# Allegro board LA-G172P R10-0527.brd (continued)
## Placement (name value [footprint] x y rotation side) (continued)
CT361  1U_0201_6.3V6K  [C_0201]  17.37 38.84 180 top
CT362  470P_0402_50V7K  [C_0402]  14.5 39.03 0 top
CT363  0.1U_0201_10V6K  [C_0201]  12.42 37.86 270 top
CT365  47U_0603_6.3V6M  [C_0603]  17.11 44.61 0 top
CT366  47U_0603_6.3V6M  [C_0603]  285.21 36.36 270 top
CV633  2200P_0402_50V7K  [C_0402]  123.91 80.45 0 bottom
CV651  2200P_0402_50V7K  [C_0402]  132.25 83.65 0 bottom
CW1  0.1U_0201_10V6K  [C_0201]  191.17 69.91 90 bottom
CW2  0.01U_0201_16V7  [C_0201]  179.29 69.98 90 bottom
CW3  10U_0402_10V6M  [C_0402]  176.96 68.64 180 bottom
CW4  15P_0201_50V8J  [C_0201]  190.6 69.91 90 bottom
CW5  2P_0201_25V8B  [C_0201]  98.9 76.31 270 bottom
CW6  2P_0201_25V8B  [C_0201]  97.71 76.94 180 bottom
CW7  2P_0201_25V8B  [C_0201]  198.5 77.44 90 bottom
CW8  2P_0201_25V8B  [C_0201]  200.35 78.13 180 bottom
CW9  10U_0402_10V6M  [C_0402]  191.4 68.64 180 bottom
CW10  0.01U_0201_16V7  [C_0201]  191.74 69.91 90 bottom
CW11  15P_0201_50V8J  [C_0201]  178.72 69.98 90 bottom
CW12  0.1U_0201_10V6K  [C_0201]  178.15 69.98 90 bottom
D1  -  [BAT54CW_SOT323-3]  104.87 66.05 0 top
D2  -  [BAT54CW_SOT323-3]  187.44 39.95 90 top
D3  -  [BAT54CW_SOT323-3]  187.23 42.9 270 top
D12  -  [RB751V40_SC76-2]  235.06 5.2 270 top
D13  AZ5B75-01B.R7G_CSP0603P2Y2  [AZ5B75-01BPR7G_CSP0603P2Y2]  61.06 16.37 270 top
D14  AZ5B75-01B.R7G_CSP0603P2Y2  [AZ5B75-01BPR7G_CSP0603P2Y2]  61.06 17.11 90 top
D16  -  [TVNST52302AB0_SOT523-3]  62.25 14.51 270 top
D20  -  [RB751S40T1G_SOD523-2]  235.49 16.08 90 top
D21  -  [RB751S40T1G_SOD523-2]  186.15 46.48 270 top
D23  -  [BAT54CW_SOT323-3]  175.74 59.6 180 top
D50  PESD5V0H1BSF_SOD962-2-2  [ESD101-B1-02ELS_TSSLP-2-4-2]  256.38 11.36 270 top
D51  PESD5V0H1BSF_SOD962-2-2  [ESD101-B1-02ELS_TSSLP-2-4-2]  254.99 11.36 270 top
D75  PESD5V0H1BSF_SOD962-2-2  [ESD101-B1-02ELS_TSSLP-2-4-2]  12.8 65.47 90 top
D76  PESD5V0H1BSF_SOD962-2-2  [ESD101-B1-02ELS_TSSLP-2-4-2]  12.91 59.14 90 bottom
D77  PESD5V0H1BSF_SOD962-2-2  [ESD101-B1-02ELS_TSSLP-2-4-2]  12.8 64.85 270 top
D78  PESD5V0H1BSF_SOD962-2-2  [ESD101-B1-02ELS_TSSLP-2-4-2]  12.91 60.55 270 bottom
D79  PESD5V0H1BSF_SOD962-2-2  [ESD101-B1-02ELS_TSSLP-2-4-2]  13.92 64.98 90 bottom
D80  PESD5V0H1BSF_SOD962-2-2  [ESD101-B1-02ELS_TSSLP-2-4-2]  11.9 57.97 0 top
D81  PESD5V0H1BSF_SOD962-2-2  [ESD101-B1-02ELS_TSSLP-2-4-2]  13.92 64.36 270 bottom
D82  PESD5V0H1BSF_SOD962-2-2  [ESD101-B1-02ELS_TSSLP-2-4-2]  13.3 57.97 180 top
D83  PESD5V0H1BSF_SOD962-2-2  [ESD101-B1-02ELS_TSSLP-2-4-2]  280.63 69.8 315 top
D84  PESD5V0H1BSF_SOD962-2-2  [ESD101-B1-02ELS_TSSLP-2-4-2]  275.83 71.44 315 bottom
D85  PESD5V0H1BSF_SOD962-2-2  [ESD101-B1-02ELS_TSSLP-2-4-2]  280.19 70.24 135 top
D86  PESD5V0H1BSF_SOD962-2-2  [ESD101-B1-02ELS_TSSLP-2-4-2]  276.83 70.44 135 bottom
D87  PESD5V0H1BSF_SOD962-2-2  [ESD101-B1-02ELS_TSSLP-2-4-2]  280.63 69.8 315 bottom
D88  PESD5V0H1BSF_SOD962-2-2  [ESD101-B1-02ELS_TSSLP-2-4-2]  275.92 71.09 315 top
D89  PESD5V0H1BSF_SOD962-2-2  [ESD101-B1-02ELS_TSSLP-2-4-2]  280.19 70.24 135 bottom
D90  PESD5V0H1BSF_SOD962-2-2  [ESD101-B1-02ELS_TSSLP-2-4-2]  276.92 70.09 135 top
D116  RB751S40T1G_SOD523-2  [RB520SM-30T2R_EMD2-2]  179.46 16.36 0 top
D132  -  [RB751V40_SC76-2]  65.56 17.27 270 top
D407  PESD5V0H1BSF_SOD962-2-2  [ESD101-B1-02ELS_TSSLP-2-4-2]  11.58 62.83 90 top
D408  PESD5V0H1BSF_SOD962-2-2  [ESD101-B1-02ELS_TSSLP-2-4-2]  11.58 61.81 90 top
D409  PESD5V0H1BSF_SOD962-2-2  [ESD101-B1-02ELS_TSSLP-2-4-2]  12.91 61.95 270 bottom
D410  PESD5V0H1BSF_SOD962-2-2  [ESD101-B1-02ELS_TSSLP-2-4-2]  12.91 62.96 270 bottom
D411  PESD5V0H1BSF_SOD962-2-2  [ESD101-B1-02ELS_TSSLP-2-4-2]  12.35 63.66 0 top
D412  PESD5V0H1BSF_SOD962-2-2  [ESD101-B1-02ELS_TSSLP-2-4-2]  11.58 60.73 90 top
D413  PESD5V0H1BSF_SOD962-2-2  [ESD101-B1-02ELS_TSSLP-2-4-2]  12.59 66.99 90 top
D414  PESD5V0H1BSF_SOD962-2-2  [ESD101-B1-02ELS_TSSLP-2-4-2]  13.56 64.05 270 top
D415  PESD5V0H1BSF_SOD962-2-2  [ESD101-B1-02ELS_TSSLP-2-4-2]  278.17 69.24 0 top
D416  PESD5V0H1BSF_SOD962-2-2  [ESD101-B1-02ELS_TSSLP-2-4-2]  277.15 69.24 0 top
D417  PESD5V0H1BSF_SOD962-2-2  [ESD101-B1-02ELS_TSSLP-2-4-2]  278.16 70.31 135 bottom
D418  PESD5V0H1BSF_SOD962-2-2  [ESD101-B1-02ELS_TSSLP-2-4-2]  278.88 69.59 135 bottom
D419  PESD5V0H1BSF_SOD962-2-2  [ESD101-B1-02ELS_TSSLP-2-4-2]  273.4 63.45 180 bottom
D420  PESD5V0H1BSF_SOD962-2-2  [ESD101-B1-02ELS_TSSLP-2-4-2]  273.2 69.12 0 top
D421  PESD5V0H1BSF_SOD962-2-2  [ESD101-B1-02ELS_TSSLP-2-4-2]  272.12 69.12 0 top
D422  PESD5V0H1BSF_SOD962-2-2  [ESD101-B1-02ELS_TSSLP-2-4-2]  272.17 63.5 180 bottom
D438  -  [RB751S40T1G_SOD523-2]  204.78 54.08 180 top
D444  PESD5V0H1BSF_SOD962-2-2  [ESD101-B1-02ELS_TSSLP-2-4-2]  163.99 80.53 90 bottom
D445  PESD5V0H1BSF_SOD962-2-2  [ESD101-B1-02ELS_TSSLP-2-4-2]  165.01 80.53 90 bottom
D446  PESD5V0H1BSF_SOD962-2-2  [ESD101-B1-02ELS_TSSLP-2-4-2]  162.15 80.53 90 bottom
D447  PESD5V0H1BSF_SOD962-2-2  [ESD101-B1-02ELS_TSSLP-2-4-2]  163.16 80.53 90 bottom
D448  PESD5V0H1BSF_SOD962-2-2  [ESD101-B1-02ELS_TSSLP-2-4-2]  161.07 80.53 90 bottom
D449  PESD5V0H1BSF_SOD962-2-2  [ESD101-B1-02ELS_TSSLP-2-4-2]  160.05 80.53 90 bottom
D450  PESD5V0H1BSF_SOD962-2-2  [ESD101-B1-02ELS_TSSLP-2-4-2]  158.53 79.26 90 bottom
D459  AZ4520-01F.R7G_DFN1610P2E2  [AZ4520-01FPR7G_DFN1610P2E2]  8.69 54.4 180 top
D460  AZ4520-01F.R7G_DFN1610P2E2  [AZ4520-01FPR7G_DFN1610P2E2]  283.64 62.42 0 top
D461  LMBR4010H3T5G DFN-1608  [NSR20F30NXT5G_DSN2-2]  9.73 17.51 315 bottom
D462  LMBR4010H3T5G DFN-1608  [NSR20F30NXT5G_DSN2-2]  272.82 16.28 90 top
D465  PESD5V0H1BSF_SOD962-2-2  [ESD101-B1-02ELS_TSSLP-2-4-2]  130.78 81.48 90 bottom
D466  PESD5V0H1BSF_SOD962-2-2  [ESD101-B1-02ELS_TSSLP-2-4-2]  129.13 81.48 90 bottom
D468  -  [RB751S40T1G_SOD523-2]  186.32 35.91 0 top
D469  -  [BZT52C6V2LP-7_X1-DFN1006-2-2]  70.33 6.67 270 top
D470  -  [BZT52C6V2LP-7_X1-DFN1006-2-2]  233.3 10.39 180 top
D471  PESD5V0H1BSF_SOD962-2-2  [ESD101-B1-02ELS_TSSLP-2-4-2]  129.95 81.48 90 bottom
D472  PESD5V0H1BSF_SOD962-2-2  [ESD101-B1-02ELS_TSSLP-2-4-2]  254.16 11.36 270 top
D473  PESD5V0H1BSF_SOD962-2-2  [ESD101-B1-02ELS_TSSLP-2-4-2]  253.33 11.36 270 top
D474  -  [RB751S40T1G_SOD523-2]  203.21 52.81 0 top
D475  -  [RB751S40T1G_SOD523-2]  203.21 51.54 0 top
D476  PESD5V0H1BSF_SOD962-2-2  [ESD101-B1-02ELS_TSSLP-2-4-2]  250.44 10.39 0 top
D477  PESD5V0H1BSF_SOD962-2-2  [ESD101-B1-02ELS_TSSLP-2-4-2]  251.83 10.39 180 top
D481  -  [RB751V40_SC76-2]  206.76 64.25 270 bottom
DA1  -  [ESD207-B1-02EL_TSLP-2-19-2]  10.06 74.87 90 bottom
DA3  -  [ESD207-B1-02EL_TSLP-2-19-2]  5.37 74.2 180 bottom
DA4  -  [ESD207-B1-02EL_TSLP-2-19-2]  13.35 71.79 0 top
DA5  -  [ESD207-B1-02EL_TSLP-2-19-2]  5.37 75.22 180 bottom
DA8  AZ5B75-01B.R7G_CSP0603P2Y2  [AZ5B75-01BPR7G_CSP0603P2Y2]  13.75 5.64 0 bottom
DA9  AZ5B75-01B.R7G_CSP0603P2Y2  [AZ5B75-01BPR7G_CSP0603P2Y2]  12.04 5.64 0 bottom
DA10  -  [RB751S40T1G_SOD523-2]  27.59 11.62 270 top
DA11  AZ5125-01H.R7G_SOD523-2  [AZ5125-01HPR7G_SOD523-2]  39.91 14.5 270 top
DA13  -  [ESD207-B1-02EL_TSLP-2-19-2]  11.74 67.93 270 top
DA14  AZ5B75-01B.R7G_CSP0603P2Y2  [AZ5B75-01BPR7G_CSP0603P2Y2]  8.59 5.62 0 bottom
DA15  AZ5B75-01B.R7G_CSP0603P2Y2  [AZ5B75-01BPR7G_CSP0603P2Y2]  10.32 5.64 0 bottom
DC1  RB751S40T1G_SOD523-2  [RB520SM-30T2R_EMD2-2]  179.29 51.96 90 top
DC2  RB751S40T1G_SOD523-2  [RB520SM-30T2R_EMD2-2]  180.56 53.65 270 top
DE1  -  [RB520SM-30T2R_EMD2-2]  211.77 47.66 0 top
DE2  -  [RB520SM-30T2R_EMD2-2]  220.68 63.05 180 top
DE3  -  [RB520SM-30T2R_EMD2-2]  218.97 46.01 90 top
DE4  -  [RB520SM-30T2R_EMD2-2]  221.2 56.07 270 top
DE5  -  [RB520SM-30T2R_EMD2-2]  211.77 46.46 0 top
DT1  -  [1N4148WS-L_SOD323-2]  9.66 25.44 135 top
DT2  -  [1N4148WS-L_SOD323-2]  258.7 19.4 180 top
DV11  RB751S40T1G_SOD523-2  [RB520SM-30T2R_EMD2-2]  123.62 81.49 0 bottom
DV12  RB751S40T1G_SOD523-2  [RB520SM-30T2R_EMD2-2]  131.25 83.67 180 bottom
DZ3  -  [RB751S40T1G_SOD523-2]  196.91 61.31 180 top
DZ4  -  [RB751S40T1G_SOD523-2]  196.91 60.04 180 top
F1  0.5A_65V_T0603FF0500TM  [F_T0603FF0500TM]  68.32 19.92 90 top
F2  0438.500WR 0.5A 32V UL/CSA  [R_0603]  63.3 18.11 180 top
F3  3A_32V_F0603FA3000V032T  [F_F0603FA3000V032T]  100.86 70.97 180 top
F4  1A_65V_T0603FF1000TM  [F_T0603FF1000TM]  173.32 70.28 90 top
F5  0.5A_65V_T0603FF0500TM  [F_T0603FF0500TM]  165.96 82.15 90 bottom
FD1  -  [FIDUCIAL_C40M80]  19.53 66.14 0 top
FD2  -  [FIDUCIAL_C40M80]  274.31 46.38 0 top
FD3  -  [FIDUCIAL_C40M80]  19.65 64.74 180 bottom
FD4  -  [FIDUCIAL_C40M80]  282.35 3.47 180 bottom
H1  H_2P0  [H_2P0-G]  2.9 71.75 0 top
H2  H_2P0  [H_2P0-G]  26.8 57.75 0 top
H3  H_2P0  [H_2P0-G]  24.13 29.27 0 top
H4  -  [H_2P0]  64.38 21.91 0 top
H5  -  [H_2P4]  232.12 20.4 0 top
H6  H_2P0  [H_2P0-G]  268.67 29.27 0 top
H7  H_2P0  [H_2P0-G]  266 57.75 0 top
H8  H_2P9  [H_2P9-G]  2.9 53.35 0 top
H9  H_2P0  [H_2P0-G]  118.26 46.9 0 top
H10  H_2P0  [H_2P0-G]  182.54 46.9 0 top
H11  H_2P0  [H_2P0-G]  118.26 25.17 0 top
H12  H_2P0  [H_2P0-G]  182.54 25.17 0 top
H13  -  [H_2P4]  117.83 20.4 0 top
H14  -  [H_2P6]  176.4 78.95 0 top
H15  -  [H_2P6]  110.55 78.95 0 top
H16  H_2P6  [H_2P6-G]  195.05 71.85 0 top
H17  H_1P9  [H_1P9-G]  19.05 71.25 0 top
H18  H_1P9  [H_1P9-G]  92.27 71.85 0 top
H19  H_1P9  [H_1P9-G]  148.5 80 0 top
H20  H_1P9  [H_1P9-G]  200.55 71.85 0 top
H21  H_1P9  [H_1P9-G]  287.9 83.35 0 top
H22  -  [H_2P4]  222.6 2.35 0 top
H23  -  [H_2P4]  70.2 2.35 0 top
H24  -  [H_2P4]  2.18 3.11 0 top
H25  -  [H_2P4]  290.62 3.11 0 top
H27  -  [H_1P3N]  291.25 7.3 0 top
H29  -  [H_2P5X5P5N]  148.5 76.15 90 top
H33  -  [H_0P5X2P3N]  141.3 1.7 90 top
H34  -  [H_0P4X2P2N]  222.79 41 180 top
H35  -  [H_0P5X2P3N]  151.4 73.7 90 top
H36  -  [H_0P5X2P3N]  141.3 73.7 90 top
H37  -  [H_0P5X2P3N]  79.55 73.7 90 top
H38  -  [H_0P5X2P3N]  151.4 1.7 90 top
JANTL1  RF_SPRING  [CLIP_2X2P5-NP]  97.96 80.19 90 top
JANTL3  BELLW_10093-1021  [BELLW_10093-1021_4P]  109.57 74.25 90 bottom
JANTR1  BELLW_10093-1021  [BELLW_10093-1021_4P]  177.38 74.25 270 bottom
JANTR3  RF_SPRING  [CLIP_2X2P5-NP]  201.03 80.19 90 top
JAPS1  ACES_50506-01841-P01  [ACES_50506-01841-P01_18P]  217.39 62.77 270 bottom
JCR1  T-SOL_158-9090302600  [T-SOL_158-9090302600_18P-T]  276.79 51.04 90 top
JDB1  ACES_50521-01041-P01  [ACES_50521-01041-P01_10P]  11 32.71 90 bottom
JDB2  ACES_50521-01041-P01  [ACES_50521-01041-P01_10P]  256.23 10.41 0 bottom
JDB3  JXT_FP241AH-006GAAM  [JXT_FP241AH-006GAAM_6P]  7.29 45.59 90 bottom
JDB4  JXT_FP241AH-006GAAM  [JXT_FP241AH-006GAAM_6P]  287.35 27.07 270 bottom
JDEBUG1  ACES_50521-01041-P01  [ACES_50521-01041-P01_10P]  229.18 7.82 270 top
JDEBUG2  ACES_50521-01041-P01  [ACES_50521-01041-P01_10P]  208.03 69.14 0 bottom
JDEG1  -  [ACES_50521-01041-P01_10P]  230.69 3.31 90 top
JEDP1  I-PEX_20879-040E-01  [I-PEX_20879-040E-01_40P-T]  140.9 83.92 0 top
JFAN1  CVILU_CF35042D0RD-NH  [CVILU_CF35042D0RD-NH_4P-T]  63.45 2.64 180 top
JFAN2  CVILU_CF35042D0RD-NH  [CVILU_CF35042D0RD-NH_4P-T]  237.65 2.85 180 top
JFP1  TWVM_FPC0510-08RC-TAGHA  [TWVM_FPC0510-08RC-TAGHA_8P]  57.95 14.85 270 top
JHP1  UNIMI_FCECBE015  [UNIMI_FCECBE015_6P-T]  8.22 75.1 90 top
JIO1  ACES_51515-0510M-P01  [ACES_51515-0510M-P01_51P-T]  243.65 5.63 0 top
JMIPI60  SAMTE_QSH-030-01-L-D-A  [SAMTE_QSH-030-01-H-D-A_60P-T]  110 11.99 0 bottom
JNGFF1  BELLW_80149-2021  [BELLW_80149-2021_67P-S]  218.64 12.8 180 bottom
JRTC1  ACES_50278-00201-001  [ACES_50278-00201-001_2P]  56.57 11.95 0 top
JSP1  EMIST_SU-15AG  [EMIST_SU-15AG_1P-T]  131.15 76.69 90 bottom
JSP2  EMIST_SU-15AG  [EMIST_SU-15AG_1P-T]  143 76.69 90 bottom
JSP3  EMIST_SU-15AG  [EMIST_SU-15AG_1P-T]  189 76.7 90 bottom
JSP4  -  [EMIST_CL-XXG0629_1P]  74.8 77.62 90 top
JSP5  -  [EMIST_CL-XXG0629_1P]  83.8 77.62 90 top
JSP6  -  [EMIST_CL-XXG0629_1P]  103.9 77.62 90 top
JSP7  -  [EMIST_CL-XXG0629_1P]  115.5 77.62 90 top
JSP8  -  [EMIST_CL-XXG0629_1P]  208.9 77.62 90 top
JSP9  -  [EMIST_CL-XXG0629_1P]  185.9 76.02 90 top
JSP10  -  [EMIST_CL-XXG0629_1P]  218.8 77.62 90 top
JSPI1  -  [ACES_50521-01041-P01_10P]  186.43 44.51 270 bottom
JSPK1  ACES_50208-00801-003  [ACES_50208-00801-003_8P]  13.01 5.6 0 top
JSSD1  ACES_51524-0240N-001  [ACES_51524-0240N-001_24P]  206.47 48.56 270 bottom
JT101  UNIMI_LLGCBE018  [UNIMI_LLGCBE018_6P-T]  38.84 5.7 0 top
JTAG2  @SHORT PADS~D  [SHORTPADS]  219.3 52.42 0 top
JUART1  CVILU_CI1804M1VRA-NH  [CVILU_CI1804M1VRA-NH_4P]  186.92 34.34 180 bottom
JUFC1  I-PEX_20879-030E-01  [I-PEX_20879-030E-01_30P-T]  167.5 83.92 0 top
JUSBC1  FOX_UT12123-10001-7H  [FOX_UT12123-10001-7H_24P-T]  9.34 65.17 270 top
JUSBC2  FOX_UT12123-10001-7H  [FOX_UT12123-10001-7H_24P-T]  283.46 71.23 90 top
L12  BLM15PX330SN1D_2P  [MURAT_BLM15PX330SN1D_2P]  12.22 74.28 135 bottom
L15  BLM15PX330SN1D_2P  [MURAT_BLM15PX330SN1D_2P]  8.56 75.31 270 bottom
L24  1.8NH +-0.1NH LQP03TN1N8B02D  [MURAT_LQP03TN1N8B00D_2P]  98.26 76.31 180 bottom
L26  HCM1012GH900BP_4P  [INPAQ_HCM1012GH900BP_4P]  182.85 52.23 90 top
L27  1.2NH_LQP03TN1N2B02D_0.1NH  [MURAT_LQP03TN1N2B02D_2P]  197.31 77.44 0 bottom
LA1  HCB2012KF-600T30  [TAI-T_HCB2012KF-121T50_2P]  38.21 18.13 0 top
LA2  HCB1608KF-121T30_0603  [TAI-T_HCB1608KF-121T3_L0603_2P]  22.73 12.74 0 top
LA5  BLM18SG260TN1D_2P  [MURAT_BLM18SG260TN1D_2P]  7.99 8.7 270 bottom
LA6  BLM18SG260TN1D_2P  [MURAT_BLM18SG260TN1D_2P]  9.96 8.7 270 bottom
LA7  BLM18SG260TN1D_2P  [MURAT_BLM18SG260TN1D_2P]  11.61 8.7 270 bottom
LA8  BLM18SG260TN1D_2P  [MURAT_BLM18SG260TN1D_2P]  13.38 8.7 270 bottom
LA18  BLM15AX700SN1D_2P  [MURAT_BLM15AX700SN1D_2P]  14.2 70.81 180 top
LA19  BLM15AX700SN1D_2P  [MURAT_BLM15AX700SN1D_2P]  6.49 74.73 90 bottom
LC1  0.68UH_UHP252012NF-R68M_3A_20%  [TAI-T_UHP252012NF-R68M_2P]  178.72 33.69 0 top
LC2  BLM18EG221TN1D_2P~D  [MURAT_BLM18EG221SN1D_2P]  179.38 38.58 180 top
LED1  HT-F196BP5_WHITE  [LED_HT-F196BP5_2P]  202.93 56.3 0 bottom
LED2  HT-F196BP5_WHITE  [LED_HT-F196BP5_2P]  204.43 57.5 180 bottom
LS2  HCB1608KF-121T30_0603  [MURAT_BLM18EG221SN1D_2P]  190.3 16.8 0 top
LT1  HCB2012KF-800T50_2P  [TAI-T_HCB2012KF-121T50_2P]  10.51 55.05 270 top
LT2  HCB2012KF-800T50_2P  [TAI-T_HCB2012KF-121T50_2P]  286.93 65.21 270 top
LT3  BLM18KG331SN1D_2P  [MURAT_BLM18KG331SN1D_2P]  13.95 35.91 180 top
LT5  0.68UH_MLV-YT10NR68N-M1L_2.7A_30%  [MAG_MLV-YT10NR68N-M1L_2P]  283.69 33.49 270 top
LT8  0.68UH_MLV-YT10NR68N-M1L_2.7A_30%  [MAG_MLV-YT10NR68N-M1L_2P]  17.81 43.39 270 top
LT9  HCB2012KF-800T50_2P  [TAI-T_HCB2012KF-121T50_2P]  67.91 7.43 270 top
LT10  HCB2012KF-800T50_2P  [TAI-T_HCB2012KF-121T50_2P]  235.02 8.25 270 top
LT11  HCB2012KF-800T50_2P  [TAI-T_HCB2012KF-121T50_2P]  4.89 16.91 90 top
LT12  HCB2012KF-800T50_2P  [TAI-T_HCB2012KF-121T50_2P]  269.07 13.59 90 top
LT13  HCB2012KF-800T50_2P  [TAI-T_HCB2012KF-121T50_2P]  3.08 16.91 90 top
LT14  HCB2012KF-800T50_2P  [TAI-T_HCB2012KF-121T50_2P]  270.85 13.59 90 top
LT15  BLM18KG331SN1D_2P  [MURAT_BLM18KG331SN1D_2P]  287.5 31.96 90 top
LV1  BLM15PX221SN1D_2P  [MURAT_BLM15PX221SN1D_2P]  133.26 81.25 0 bottom
ML1  HCM1012GH900BP_4P  [INPAQ_HCM1012GH900BP_4P]  196.11 66.59 180 top
ML6  HCM1012GH900BP_4P  [INPAQ_HCM1012GH900BP_4P]  13.8 62.27 180 top
ML7  HCM1012GH900BP_4P  [INPAQ_HCM1012GH900BP_4P]  15.14 62.52 180 bottom
ML16  HCM1012GH900BP_4P  [INPAQ_HCM1012GH900BP_4P]  277.61 66.97 90 top
ML17  HCM1012GH900BP_4P  [INPAQ_HCM1012GH900BP_4P]  276.99 68.35 45 bottom
ML18  HCM1012GH900BP_4P  [INPAQ_HCM1012GH900BP_4P]  63.27 16.49 180 top
NOREF  -  []  110.4 8.55 0 top
NOREF#2  -  []  222.6 2.35 0 top
NOREF#3  -  []  117.83 20.4 0 top
NOREF#4  -  []  19.05 71.25 0 top
NOREF#5  -  []  99.85 9.88 0 top
NOREF#6  -  []  92.27 71.85 0 top
NOREF#7  -  []  266 57.75 0 top
NOREF#8  -  []  182.54 46.9 0 top
NOREF#9  -  []  64.38 21.91 0 top
NOREF#10  -  []  268.67 29.27 0 top
NOREF#11  -  []  290.62 3.11 0 top
NOREF#12  -  []  98.63 132.27 0 top
NOREF#13  -  []  157.86 75.47 0 top
NOREF#14  -  []  200.55 71.85 0 top
NOREF#15  -  []  26.8 57.75 0 top
NOREF#16  -  []  182.54 25.17 0 top
NOREF#17  -  []  24.13 29.27 0 top
NOREF#18  -  []  118.26 25.17 0 top
NOREF#19  -  []  70.2 2.35 0 top
NOREF#20  -  []  118.26 46.9 0 top
NOREF#21  -  []  146.4 89 0 top
NOREF#22  -  []  108.05 17.29 0 top
NOREF#23  -  []  131.26 -41.78 0 top
NOREF#24  -  []  2.18 3.11 0 top
NOREF#25  -  []  287.9 83.35 0 top
NOREF#26  -  []  232.12 20.4 0 top
NOREF#27  -  []  148.5 80 0 top
NOREF#28  -  []  167.1 -28.7 180 bottom
NOREF#29  -  []  148.24 47.47 180 bottom
NOREF#30  -  []  75.34 25.04 180 bottom
NOREF#31  -  []  141.51 46.84 180 bottom
NOREF#32  -  []  134.34 11.59 180 bottom
NOREF#33  -  []  94.2 12.61 270 bottom
PC100  2200P_0402_50V7K  [C_0402]  100.6 14.71 0 top
PC101  1000P_0402_50V7K  [C_0402]  101.52 15.59 180 top
PC102  0.01U_0402_25V7K  [C_0402]  97.74 17.06 270 top
PC200  0.1U_0402_25V6  [C_0402]  71.9 21.03 0 top
PC201  0.1U_0402_25V6  [C_0402]  79.22 24.56 270 top
PC202  2200P_0402_50V7K  [C_0402]  78.33 24.56 270 top
PC203  10U_0603-H1_2_25V6M  [C_0603-H1_2]  76.06 24.85 270 top
PC204  10U_0603-H1_2_25V6M  [C_0603-H1_2]  76.56 27.29 90 top
PC205  10U_0603-H1_2_25V6M  [C_0603-H1_2]  75.37 27.29 90 top
PC206  10U_0603-H1_2_25V6M  [C_0603-H1_2]  77.25 24.85 270 top
PC207  10U_0603-H1_2_25V6M  [C_0603-H1_2]  78.95 27.29 90 top
PC208  10U_0603-H1_2_25V6M  [C_0603-H1_2]  77.75 27.29 90 top
PC209  10U_0603-H1_2_25V6M  [C_0603-H1_2]  74.17 27.29 90 top
PC210  4.7U_0402_16V6M  [C_0402]  78.48 15.33 90 top
PC211  0.1U_0402_25V6  [C_0402]  72.84 19.23 270 top
PC212  1U_0402_25V6K  [C_0402]  77.46 15.25 180 top
PC213  1U_0402_25V6K  [C_0402]  76.74 17.8 90 top
PC214  10U_0603-H1_2_25V6M  [C_0603-H1_2]  85.13 45.58 90 top
PC215  10U_0603-H1_2_25V6M  [C_0603-H1_2]  86.47 45.61 90 top
PC216  10U_0603-H1_2_25V6M  [C_0603-H1_2]  86.22 42.39 270 top
PC217  10U_0603-H1_2_25V6M  [C_0603-H1_2]  84.98 42.36 270 top
PC218  33U_B3_16VM_R45M  [C_B3]  90.12 53.1 180 top
PC219  33U_B3_16VM_R45M  [C_B3]  90.17 49.8 180 top
PC221  10U_0603-H1_2_25V6M  [C_0603-H1_2]  83.74 42.34 270 top
PC222  10U_0603-H1_2_25V6M  [C_0603-H1_2]  83.77 45.54 90 top
PC223  0.1U_0402_25V6  [C_0402]  88.54 47.74 180 top
PC224  2200P_0402_50V7K  [C_0402]  87.57 45.93 90 top
PC225  0.22U_0603_25V7K  [C_0603]  76.81 20.35 0 top
PC226  1U_0402_25V6K  [C_0402]  78.64 14.19 180 top
PC227  1U_0402_25V6K  [C_0402]  81.63 10.64 90 top
PC228  2.2U_0402_6.3V6M  [C_0402]  79.6 21.28 90 top
PC229  2.2U_0402_6.3V6M  [C_0402]  81.55 12.77 90 top
PC230  0.22U_0603_25V7K  [C_0603]  82.73 21.65 90 top
PC231  10U_0603_25V6M  [C_0603]  92.81 18.33 270 top
PC232  10U_0603_25V6M  [C_0603]  91.55 18.32 270 top
PC233  4700P_0402_25V7K  [C_0402]  95.15 17.05 180 top
PC234  2200P_0402_50V7K  [C_0402]  98.66 17.05 270 top
PC235  0.1U_0402_25V6  [C_0402]  86.16 22.91 180 top
PC236  680P_0402_50V7K  [C_0402]  87.21 31.02 0 bottom
PC237  680P_0402_50V7K  [C_0402]  73.67 43.3 0 top
PC238  1U_0402_25V6K  [C_0402]  84.31 22.96 270 top
PC239  1U_0402_25V6K  [C_0402]  84.16 20.86 0 top
PC240  1U_0402_25V6K  [C_0402]  87.89 21.14 0 top
PC241  560P_0402_50V7K  [C_0402]  86.32 16.1 0 top
PC243  0.01U_0402_16V7K  [C_0402]  87.21 17.89 270 top
PC244  0.1U_0402_25V6  [C_0402]  219.88 70.71 180 top
PC245  0.1U_0402_25V6  [C_0402]  86.09 20.23 0 top
PC300  0.22U_0402_16V7K  [C_0402]  84.26 53.11 270 top
PC301  0.1U_0402_25V6  [C_0402]  81.77 62.57 180 top
PC302  2200P_0402_50V7K  [C_0402]  82.76 60.16 0 top
PC303  10U_0603_25V6M  [C_0603]  81.73 60.25 180 top
PC304  10U_0603_25V6M  [C_0603]  81.73 61.49 180 top
PC305  220P_0201_25V7K  [C_0201]  86.53 55.79 270 top
PC306  22U_0603_6.3V6M  [C_0603]  75.34 57.61 180 top
PC307  22U_0603_6.3V6M  [C_0603]  75.34 56.39 180 top
PC308  22U_0603_6.3V6M  [C_0603]  77.27 55.17 0 top
PC309  22U_0603_6.3V6M  [C_0603]  77.27 56.36 0 top
PC310  22U_0603_6.3V6M  [C_0603]  77.27 57.58 0 top
PC311  22U_0603_6.3V6M  [C_0603]  75.34 55.17 180 top
PC313  2.2U_0402_6.3V6M  [C_0402]  78.71 58.6 90 top
PC314  680P_0603_50V7K  [C_0603]  84.34 48.27 0 top
PC400  0.22U_0402_16V7K  [C_0402]  20.29 2.82 90 top
PC401  0.1U_0402_25V6  [C_0402]  26.19 6.15 270 top
PC402  2200P_0402_50V7K  [C_0402]  27.08 6.15 270 top
PC403  10U_0603_25V6M  [C_0603]  27.66 7.09 90 top
PC404  10U_0603_25V6M  [C_0603]  26.39 7.09 90 top
PC405  220P_0201_25V7K  [C_0201]  23.55 1.88 0 top
PC406  22U_0603_6.3V6M  [C_0603]  12.65 9.26 270 top
PC407  22U_0603_6.3V6M  [C_0603]  11.4 9.25 270 top
PC408  22U_0603_6.3V6M  [C_0603]  13.89 9.26 270 top
PC410  22U_0603_6.3V6M  [C_0603]  13.91 10.55 90 top
PC411  22U_0603_6.3V6M  [C_0603]  11.42 10.54 90 top
PC412  22U_0603_6.3V6M  [C_0603]  12.67 10.54 90 top
PC414  2.2U_0402_6.3V6M  [C_0402]  24.45 10.29 180 top
PC415  680P_0603_50V7K  [C_0603]  16.23 3.53 270 top
PC416  0.22U_0402_16V7K  [C_0402]  272.77 8.07 270 top
PC417  0.1U_0402_25V6  [C_0402]  266.93 6.84 90 top
PC418  2200P_0402_50V7K  [C_0402]  265.97 6.85 90 top
PC419  10U_0603_25V6M  [C_0603]  266.81 5.43 270 top
PC420  10U_0603_25V6M  [C_0603]  265.5 5.44 270 top
PC421  220P_0201_25V7K  [C_0201]  269.95 10.58 180 top
PC422  22U_0603_6.3V6M  [C_0603]  280.88 3.93 270 top
PC423  22U_0603_6.3V6M  [C_0603]  283.29 5.24 90 top
PC425  22U_0603_6.3V6M  [C_0603]  282.09 5.25 90 top
PC426  22U_0603_6.3V6M  [C_0603]  283.31 3.94 270 top
PC427  22U_0603_6.3V6M  [C_0603]  282.1 3.93 270 top
PC428  22U_0603_6.3V6M  [C_0603]  280.88 5.26 90 top
PC430  2.2U_0402_6.3V6M  [C_0402]  268.62 2.49 180 top
PC431  680P_0603_50V7K  [C_0603]  273.34 9.04 90 top
PC432  33U_B3_16VM_R45M  [C_B3]  28.9 3.53 0 top
PC433  33U_B3_16VM_R45M  [C_B3]  263.47 3.89 180 top
PC500  0.22U_0402_16V7K  [C_0402]  206.74 18.46 90 top
PC501  10U_0603_25V6M  [C_0603]  212.95 21.99 90 top
PC502  10U_0603_25V6M  [C_0603]  214.19 21.97 90 top
PC503  0.1U_0402_25V6  [C_0402]  212.78 21.03 270 top
PC504  2200P_0402_25V7K  [C_0402]  213.67 21.02 270 top
PC505  220P_0201_25V7K  [C_0201]  212.92 18.2 180 top
PC506  22U_0603_6.3V6M  [C_0603]  199.91 21.08 270 top
PC507  22U_0603_6.3V6M  [C_0603]  201.16 22.96 90 top
PC508  22U_0603_6.3V6M  [C_0603]  199.9 22.96 90 top
PC509  22U_0603_6.3V6M  [C_0603]  201.14 21.1 270 top
PC510  2.2U_0402_6.3V6M  [C_0402]  209.14 18.87 0 top
PC512  680P_0603_50V7K  [C_0603]  211.42 25.25 270 top
PC600  2.2U_0402_10V6M  [C_0402]  91.33 6.45 0 top
PC700  22U_0805_25V6M  [C_0805]  95.64 56.49 0 top
PC701  22U_0805_25V6M  [C_0805]  95.64 54.77 0 top
PC702  22U_0805_25V6M  [C_0805]  95.64 65.14 0 top
PC703  22U_0805_25V6M  [C_0805]  95.65 66.86 0 top
PC704  0.1U_0402_25V6  [C_0402]  95.68 63.83 0 top
PC705  0.1U_0402_25V6  [C_0402]  95.68 57.8 0 top
PC706  0.1U_0402_25V6  [C_0402]  100.16 63.81 270 top
PC708  47U_0603_6.3V6M  [C_0603]  102.51 54.85 180 top
PC709  47U_0603_6.3V6M  [C_0603]  103.62 57.7 0 top
PC710  47U_0603_6.3V6M  [C_0603]  103.62 56.45 0 top
PC711  100P_0402_50V8J  [C_0402]  93.2 64.04 180 top
PC712  47U_0603_6.3V6M  [C_0603]  102.54 52.31 180 top
PC713  4.7U_0402_16V6M  [C_0402]  92.49 59.9 180 top
PC714  0.1U_0402_25V6  [C_0402]  92.63 61.7 180 top
PC715  680P_0603_50V7K  [C_0603]  102.9 64.87 180 top
PC716  47U_0603_6.3V6M  [C_0603]  102.53 53.62 180 top
PC801  0.22U_0402_16V7K  [C_0402]  78.25 66.84 0 top
PC802  10U_0603_25V6M  [C_0603]  84.04 68.48 90 top
PC803  10U_0603_25V6M  [C_0603]  85.26 68.47 90 top
PC804  0.1U_0402_25V6  [C_0402]  84.79 67.52 270 top
PC805  2200P_0402_25V7K  [C_0402]  83.87 67.51 270 top
PC806  22U_0603_6.3V6M  [C_0603]  75.13 68.69 180 top
PC807  22U_0603_6.3V6M  [C_0603]  75.14 66.28 180 top
PC808  22U_0603_6.3V6M  [C_0603]  75.12 69.88 180 top
PC809  22U_0603_6.3V6M  [C_0603]  75.13 67.49 180 top
PC810  2.2U_0402_6.3V6M  [C_0402]  80.66 66.01 0 top
PC811  680P_0402_50V7K  [C_0402]  76.05 71.16 180 top
PC900  1U_0402_16V6K  [C_0402]  140 13.44 180 top
PC901  1U_0402_25V6K  [C_0402]  144.78 14.07 270 top
PC902  10U_0603_25V6M  [C_0603]  137.68 9.2 270 top
PC903  33U_B3_16VM_R45M  [C_B3]  134.17 8.65 270 top
PC904  10U_0603_25V6M  [C_0603]  136.93 10.97 90 top
PC905  10U_0603_25V6M  [C_0603]  136.47 9.2 270 top
PC906  10U_0603_25V6M  [C_0603]  138.88 9.2 270 top
PC907  10U_0603_25V6M  [C_0603]  135.72 10.97 90 top
PC908  10U_0603_25V6M  [C_0603]  138.14 10.97 90 top
PC909  1U_0402_16V6K  [C_0402]  139.18 10.9 90 top
PC910  1U_0402_25V6K  [C_0402]  144.8 6.35 90 top
PC911  0.1U_0201_25V6K  [C_0201]  142.31 5.5 180 top
PC912  680P_0603_50V7K  [C_0603]  148.69 5.75 0 top
PC1000  150U_B3_6.3VM_R35M  [C_TEPSLB30J157M-35-8R]  162.06 8.56 270 top
PC1001  150U_B3_6.3VM_R35M  [C_TEPSLB30J157M-35-8R]  155.69 8.56 270 top
PC1002  150U_B3_6.3VM_R35M  [C_TEPSLB30J157M-35-8R]  168.15 8.55 270 top
PC1004  22U_0603_6.3V6M  [C_0603]  156.75 10.49 90 top
PC1005  22U_0603_6.3V6M  [C_0603]  154.64 14.25 270 top
PC1006  22U_0603_6.3V6M  [C_0603]  164.41 7.54 270 top
PC1007  22U_0603_6.3V6M  [C_0603]  159.64 7.51 270 top
PC1008  22U_0603_6.3V6M  [C_0603]  158.82 14.26 270 top
PC1009  22U_0603_6.3V6M  [C_0603]  163.03 14.24 270 top
PC1010  22U_0603_6.3V6M  [C_0603]  169.36 12.78 0 top
PC1011  22U_0603_6.3V6M  [C_0603]  160.95 10.52 90 top
PC1012  22U_0603_6.3V6M  [C_0603]  169.35 14.92 0 top
PC1013  22U_0603_6.3V6M  [C_0603]  169.34 10.65 0 top
PC1014  10U_0402_6.3V6M  [C_0402]  169.4 11.72 0 top
PC1015  10U_0402_6.3V6M  [C_0402]  155.68 13.89 270 top
PC1016  10U_0402_6.3V6M  [C_0402]  159.88 13.93 270 top
PC1017  10U_0402_6.3V6M  [C_0402]  161.98 13.95 270 top
PC1018  10U_0402_6.3V6M  [C_0402]  157.79 10.8 90 top
PC1019  10U_0402_6.3V6M  [C_0402]  155.7 10.78 90 top
PC1020  10U_0402_6.3V6M  [C_0402]  159.9 10.79 90 top
PC1021  10U_0402_6.3V6M  [C_0402]  164.99 11.56 180 top
PC1022  10U_0402_6.3V6M  [C_0402]  164.95 14.57 180 top
PC1023  10U_0402_6.3V6M  [C_0402]  163.1 20.99 180 top
PC1024  47U_0603_6.3V6M  [C_0603]  158.13 7.53 270 top
PC1025  47U_0603_6.3V6M  [C_0603]  160.93 14.26 270 top
PC1026  47U_0603_6.3V6M  [C_0603]  156.72 14.27 270 top
PC1027  47U_0603_6.3V6M  [C_0603]  154.66 10.5 90 top
PC1028  47U_0603_6.3V6M  [C_0603]  165.8 7.54 270 top
PC1029  47U_0603_6.3V6M  [C_0603]  158.85 10.5 90 top
PC1030  47U_0603_6.3V6M  [C_0603]  163.04 10.49 90 top
PC1031  10U_0402_6.3V6M  [C_0402]  164.96 13.09 180 top
PC1032  10U_0402_6.3V6M  [C_0402]  165.56 21.94 0 top
PC1033  10U_0402_6.3V6M  [C_0402]  163.1 21.92 180 top
PC1034  10U_0402_6.3V6M  [C_0402]  162 10.82 90 top
PC1035  10U_0402_6.3V6M  [C_0402]  139.95 22.03 270 top
PC1036  10U_0402_6.3V6M  [C_0402]  157.77 13.95 270 top
PC1037  10U_0402_6.3V6M  [C_0402]  169.45 13.85 0 top
PC1038  10U_0402_6.3V6M  [C_0402]  140.87 22.03 270 top
PC1039  10U_0402_6.3V6M  [C_0402]  141.84 22.03 270 top
PC1050  150U_B3_6.3VM_R35M  [C_TEPSLB30J157M-35-8R]  171.35 8.56 270 top
PC1051  15P_0201_50V8J  [C_0201]  150.93 14.25 180 top
PC1052  15P_0201_50V8J  [C_0201]  157.44 16.09 180 top
PC1053  15P_0201_50V8J  [C_0201]  164.82 15.31 180 top
PC1054  15P_0201_50V8J  [C_0201]  161.37 20.13 0 top
PC1055  15P_0201_50V8J  [C_0201]  167.13 21.16 180 top
PC1100  2.2U_0402_6.3V6M  [C_0402]  94.81 47.04 180 top
PC1101  4.7U_0402_6.3V6M  [C_0402]  94.84 48.07 180 top
PC1102  1000P_0402_25V8J  [C_0402]  94.82 46.14 180 top
PC1103  150P_0402_50V8J  [C_0402]  98.85 42.77 180 top
PC1104  0.1U_0402_25V7K  [C_0402]  94.82 45.25 180 top
PC1105  390P_0402_50V7K  [C_0402]  100.76 41.76 180 top
PC1106  0.1U_0201_25V6K  [C_0201]  104.72 47.14 180 top
PC1107  330P_0402_50V8J  [C_0402]  102 45.72 0 top
PC1108  2.2U_0402_6.3V6M  [C_0402]  102.03 47.02 0 top
PC1200  0.1U_0402_25V6  [C_0402]  97.56 34.18 0 top
PC1201  1000P_0402_50V7K  [C_0402]  98.42 35.95 270 top
PC1202  1U_0402_16V6K  [C_0402]  105.1 35.7 270 top
PC1203  10U_0603-H1_2_25V6M  [C_0603-H1_2]  98.19 36.84 90 top
PC1204  10U_0603-H1_2_25V6M  [C_0603-H1_2]  99.5 35.85 270 top
PC1206  1U_0402_16V6K  [C_0402]  103.46 34.26 180 top
PC1207  0.22U_0603_25V7K  [C_0603]  104.43 33.69 0 top
PC1208  680P_0603_50V7K  [C_0603]  104.59 42.73 270 top
PC1209  33U_B3_16VM_R45M  [C_B3]  95.95 36.31 90 top
PC1210  33U_B3_16VM_R45M  [C_B3]  95.89 32.13 0 top
PC1211  33U_B3_16VM_R45M  [C_B3]  96 26.85 90 top
PC1212  33U_B3_16VM_R45M  [C_B3]  95.82 22.95 0 top
PC1213  0.1U_0402_25V6  [C_0402]  98.4 26.76 270 top
PC1214  1000P_0402_50V7K  [C_0402]  97.52 24.99 0 top
PC1215  1U_0402_16V6K  [C_0402]  105.05 26.66 270 top
PC1216  10U_0603-H1_2_25V6M  [C_0603-H1_2]  99.46 26.71 270 top
PC1217  10U_0603-H1_2_25V6M  [C_0603-H1_2]  99.43 27.73 90 top
PC1219  1U_0402_16V6K  [C_0402]  103.35 25.04 180 top
PC1220  0.22U_0603_25V7K  [C_0603]  104.77 24.8 270 top
PC1221  680P_0603_50V7K  [C_0603]  110.37 23 90 top
PC1222  10U_0603-H1_2_25V6M  [C_0603-H1_2]  99.44 36.84 90 top
PC1223  10U_0603-H1_2_25V6M  [C_0603-H1_2]  98.22 27.72 90 top
PC1300  150U_B3_6.3VM_R35M  [C_TEPSLB30J157M-35-8R]  117.13 31.39 270 top
PC1301  150U_B3_6.3VM_R35M  [C_TEPSLB30J157M-35-8R]  120.54 36.66 90 top
PC1302  150U_B3_6.3VM_R35M  [C_TEPSLB30J157M-35-8R]  120.49 31.39 270 top
PC1304  22U_0603_6.3V6M  [C_0603]  122.75 38.1 90 top
PC1305  22U_0603_6.3V6M  [C_0603]  121.76 27.05 270 top
PC1306  22U_0603_6.3V6M  [C_0603]  122.76 37.14 270 top
PC1307  22U_0603_6.3V6M  [C_0603]  122.71 30.06 270 top
PC1308  22U_0603_6.3V6M  [C_0603]  122.39 34.77 270 top
PC1309  22U_0603_6.3V6M  [C_0603]  118.13 34.77 270 top
PC1310  22U_0603_6.3V6M  [C_0603]  122.73 31.02 90 top
PC1311  22U_0603_6.3V6M  [C_0603]  123.62 34.77 270 top
PC1312  10U_0402_6.3V6M  [C_0402]  121.33 34.82 270 top
PC1313  10U_0402_6.3V6M  [C_0402]  135.86 22.02 270 top
PC1314  10U_0402_6.3V6M  [C_0402]  134.97 22.02 270 top
PC1315  10U_0402_6.3V6M  [C_0402]  123.79 38.52 90 top
PC1316  10U_0402_6.3V6M  [C_0402]  123.84 37.03 270 top
PC1317  10U_0402_6.3V6M  [C_0402]  123.79 30.12 270 top
PC1318  10U_0402_6.3V6M  [C_0402]  123.81 31.56 90 top
PC1319  10U_0402_6.3V6M  [C_0402]  122.85 27.1 270 top
PC1320  47U_0603_6.3V6M  [C_0603]  116.02 34.77 270 top
PC1321  47U_0603_6.3V6M  [C_0603]  120.27 34.76 270 top
PC1322  1U_0402_6.3V6K  [C_0402]  117.09 34.83 270 top
PC1323  1U_0402_6.3V6K  [C_0402]  119.2 34.83 270 top
PC1334  150U_B3_6.3VM_R35M  [C_TEPSLB30J157M-35-8R]  117.23 36.64 90 top
PC1335  15P_0201_50V8J  [C_0201]  112.47 33.31 180 top
PC1336  15P_0201_50V8J  [C_0201]  112.41 23.67 180 top
PC1337  15P_0201_50V8J  [C_0201]  112.47 32.69 180 top
PC1338  15P_0201_50V8J  [C_0201]  112.41 23.07 180 top
PC1339  15P_0201_50V8J  [C_0201]  122.91 24.61 180 top
PC1340  15P_0201_50V8J  [C_0201]  123.86 36.83 270 bottom
PC1341  15P_0201_50V8J  [C_0201]  121.6 34.48 270 bottom
PC1342  15P_0201_50V8J  [C_0201]  122.35 30.49 270 bottom
PC1343  15P_0201_50V8J  [C_0201]  122.99 35.95 270 bottom
PC1344  15P_0201_50V8J  [C_0201]  123.88 32.88 90 bottom
PC1345  15P_0201_50V8J  [C_0201]  124.12 29.69 270 bottom
PC1400  0.22U_0402_16V7K  [C_0402]  213.69 33.43 0 top
PC1401  0.1U_0402_25V6  [C_0402]  215.52 24.37 180 top
PC1402  2200P_0402_50V7K  [C_0402]  215.52 25.26 180 top
PC1403  10U_0603_25V6M  [C_0603]  216.44 25.12 0 top
PC1404  10U_0603_25V6M  [C_0603]  216.41 23.89 0 top
PC1405  220P_0201_25V7K  [C_0201]  212.16 28.28 270 top
PC1406  22U_0603_6.3V6M  [C_0603]  217.48 37.99 0 top
PC1407  22U_0603_6.3V6M  [C_0603]  217.48 36.8 0 top
PC1408  22U_0603_6.3V6M  [C_0603]  216.16 38 180 top
PC1409  22U_0603_6.3V6M  [C_0603]  216.14 36.79 180 top
PC1411  2.2U_0402_6.3V6M  [C_0402]  219.48 26.59 90 top
PC1412  680P_0603_50V7K  [C_0603]  219.62 29.95 270 top
PC1501  2200P_0402_25V7K  [C_0402]  199.3 7.93 270 top
PC1502  0.22U_0402_16V7K  [C_0402]  192.83 5.55 180 top
PC1503  10U_0603_25V6M  [C_0603]  200.67 8.92 90 top
PC1504  10U_0603_25V6M  [C_0603]  199.45 8.93 90 top
PC1505  0.1U_0402_25V6  [C_0402]  200.31 7.94 270 top
PC1506  220P_0201_25V7K  [C_0201]  195.13 4.64 0 top
PC1507  22U_0603_6.3V6M  [C_0603]  186.15 8.29 270 top
PC1508  22U_0603_6.3V6M  [C_0603]  187.42 8.29 270 top
PC1509  22U_0603_6.3V6M  [C_0603]  183.67 8.29 270 top
PC1510  22U_0603_6.3V6M  [C_0603]  184.94 8.29 270 top
PC1511  2.2U_0402_6.3V6M  [C_0402]  196.01 6.17 0 top
PC1512  680P_0603_50V7K  [C_0603]  195.5 11.79 0 top
PD100  -  [TVNST52302AB0_SOT523-3]  42.85 12.23 0 top
PD101  -  [TVNST52302AB0_SOT523-3]  40.18 11.84 0 top
PD200  -  [SMF4L22A_SOD123FL2]  75.39 10.51 0 top
PD201  -  [RB520SM-30T2R_EMD2-2]  77.84 8.8 180 top
PD202  -  [RB520SM-30T2R_EMD2-2]  79.79 9.09 0 top
PD600  -  [RB520SM-30T2R_EMD2-2]  83.9 6.99 0 top
PD601  -  [RB520SM-30T2R_EMD2-2]  83.9 9.52 0 top
PD602  -  [RB520SM-30T2R_EMD2-2]  83.89 8.26 0 top
PD603  -  [RB520SM-30T2R_EMD2-2]  90.81 12.29 0 top
PD604  -  [LBAT54HT1G_SOD323-2]  90.68 10.77 0 top
PJP300  PAD-OPEN 4X4M  [JUMP_43X118]  75.63 59.64 90 top
PJP400  PAD-OPEN 4X4M  [JUMP_43X118]  9.28 9.56 180 top
PJP401  PAD-OPEN 4X4M  [JUMP_43X118]  285.22 4.92 0 top
PJP500  PAD-OPEN 4X4M  [JUMP_43X118]  197.95 21.8 180 top
PJP700  PAD-OPEN 4X4M  [JUMP_43X118]  104.45 53.21 0 top
PJP800  -  [JUMP_43X79]  75.89 64.57 270 top
PJP1400  PAD-OPEN 4X4M  [JUMP_43X118]  216.76 39.94 90 top
PJP1500  PAD-OPEN 4X4M  [JUMP_43X118]  184.25 10.28 90 top
PL100  HCB2012KF-800T50_2P  [TAI-T_HCB2012KF-121T50_2P]  101.91 18.77 180 top
PL101  HCB2012KF-800T50_2P  [TAI-T_HCB2012KF-121T50_2P]  101.91 20.55 180 top
PL102  HCB2012KF-800T50_2P  [TAI-T_HCB2012KF-121T50_2P]  101.91 16.99 180 top
PL200  1UH_1277AS-H-1R0N-P2_3.3A_30%  [TOKO_1277AS-H-1R0N-P2_2P]  74.78 17.93 90 top
PL201  2.2UH_MMD-10BZN2R2M-M1L_10A_20%  [MAG_MMD-10BZN2R2M-M1L_2P]  85.72 35.25 180 top
PL300  HCB2012KF-800T50_2P  [TAI-T_HCB2012KF-121T50_2P]  84.77 61.57 180 top
PL301  1.5UH_MHCB06015-1R5M-C1_6.5A_20%  [CHILI_MHCB06015-1R5M-C1_2P]  81.89 51.06 180 top
PL302  HCB2012KF-800T50_2P  [TAI-T_HCB2012KF-121T50_2P]  84.77 63.35 180 top
PL400  HCB2012KF-800T50_2P  [TAI-T_HCB2012KF-121T50_2P]  31.05 7.81 180 top
PL401  1.5UH_MMD-05AHN1R5M-M1L_6.2A_20%  [MAG_MMD-05AHN1R5M-M1L_2P]  17.62 5.99 90 top
PL402  HCB2012KF-800T50_2P  [TAI-T_HCB2012KF-121T50_2P]  261.5 6.45 0 top
PL403  1.5UH_MMD-05AHN1R5M-M1L_6.2A_20%  [MAG_MMD-05AHN1R5M-M1L_2P]  274.13 4.61 0 top
PL404  HCB2012KF-800T50_2P  [TAI-T_HCB2012KF-121T50_2P]  31.05 6.03 180 top
PL405  HCB2012KF-800T50_2P  [TAI-T_HCB2012KF-121T50_2P]  261.5 8.23 0 top
PL500  1UH_FDSD0412-H-1R0M-P3_3.3A_20%  [TOKO_FDSD0412-H-1R0M-P3_2P]  206.86 22.1 180 top
PL501  HCB1608KF-121T30_0603  [MURAT_BLM18EG221SN1D_2P]  216.37 20.72 180 top
PL700  HCB2012KF-800T50_2P  [TAI-T_HCB2012KF-121T50_2P]  92.23 54.91 0 top
PL701  0.47UH_MMD-04AE-R47M-M1L_8A_20%  [MAG_MMD-04AE-R47M-M1L_2P]  100.69 61.11 270 top
PL800  HCB1608KF-121T30_0603  [MURAT_BLM18EG221SN1D_2P]  85.94 65.53 90 top
PL801  1UH_HEI322512A-1R0M-Q8_3.7A_20%  [CHILI_HEI322512A-1R0M-Q8_2P]  78.86 68.91 180 top
PL900  0.15UH_MHCB06024-R15M-C1R885_27A_20%  [CHILI_MHCB06024-R15M-C1R885_2P]  146.02 10.24 0 top
PL902  HCB2012KF-800T50_2P  [TAI-T_HCB2012KF-121T50_2P]  129.67 11.47 0 top
PL903  HCB2012KF-800T50_2P  [TAI-T_HCB2012KF-121T50_2P]  129.67 9.69 0 top
PL1200  0.15UH_MHCB06024-R15M-C1R885_27A_20%  [CHILI_MHCB06024-R15M-C1R885_2P]  107.45 37.25 0 top
PL1201  0.15UH_MHCB06024-R15M-C1R885_27A_20%  [CHILI_MHCB06024-R15M-C1R885_2P]  107.46 28.75 0 top
PL1202  HCB2012KF-800T50_2P  [TAI-T_HCB2012KF-121T50_2P]  91.45 26.64 0 top
PL1203  HCB2012KF-800T50_2P  [TAI-T_HCB2012KF-121T50_2P]  91.57 36.42 0 top
PL1204  HCB2012KF-800T50_2P  [TAI-T_HCB2012KF-121T50_2P]  91.45 28.55 0 top
PL1205  HCB2012KF-800T50_2P  [TAI-T_HCB2012KF-121T50_2P]  91.57 34.52 0 top
PL1400  HCB2012KF-800T50_2P  [TAI-T_HCB2012KF-121T50_2P]  217.74 22.33 180 top
PL1401  0.68UH_MHCI04015-R68M-R8_5A_20%  [CHILI_MHCI04015-R68M-R8_2P]  217.27 31.52 90 top
PL1500  HCB1608KF-121T30_0603  [MURAT_BLM18EG221SN1D_2P]  201.7 6.71 90 top
PL1501  1UH_FDSD0412-H-1R0M-P3_3.3A_20%  [TOKO_FDSD0412-H-1R0M-P3_2P]  193.13 8.33 180 top
PQ100  -  [2N7002KDW_SOT363-6]  96.38 12.98 180 top
PQ201  -  [AON6962_DFN5X6D-8-7]  80.59 29.13 270 top
PQ202  -  [AON7405_DFN8-5]  95.08 20.32 270 top
PQ203  -  [AON6962_DFN5X6D-8-7]  81.58 42.37 90 top
PQ205  -  [L2N7002WT1G_SC70-3]  86.12 11.06 270 top
PQ600  -  [L2N7002WT1G_SC70-3]  82.25 6.45 90 top
PR100  0_0402_5%  [R0402_0OHM]  94.86 10.37 270 top
PR101  200K_0201_5%  [R_0201]  94.23 12.29 90 top
PR102  0_0402_5%  [R0402_0OHM]  96.44 10.37 270 top
PR103  200K_0201_5%  [R_0201]  94.23 11.66 270 top
PR104  0_0402_5%  [R0402_0OHM]  95.65 9.46 90 top
PR105  0_0402_5%  [R_0402]  97.24 9.46 90 top
PR106  100_0402_1%  [R_0402]  41.63 9.87 0 top
PR108  100_0402_1%  [R_0402]  44.2 9.87 180 top
PR110  0_0402_5%  [R_0402]  37.82 9.87 0 top
PR134  1M_0402_5%  [R_0402]  87.9 19.35 90 top
PR200  0.01_1206_1%  [R_1206_4P-D]  74.39 22.19 90 top
PR201  442K_0402_1%  [R_0402]  71.9 20.14 0 top
PR202  1_0402_1%  [R_0402]  76.54 16.17 0 top
PR203  1_0402_1%  [R_0402]  76.54 16.93 0 top
PR204  100K_0402_1%  [R_0402]  71.93 19.2 270 top
PR205  2.2_0603_5%  [R_0603]  77.82 19.21 270 top
PR206  2_1206_5%  [R_1206]  75.79 12.62 0 top
PR207  4.7_0402_5%  [R_0402]  80.49 21.28 90 top
PR208  2_1206_5%  [R_1206]  80.12 10.49 90 top
PR210  2.2_0603_5%  [R_0603]  81.53 21.65 90 top
PR211  0.005_1206_1%  [R_1206_4P-D]  92.04 23.35 270 top
PR212  0_0201_5%  [R0201_0OHM]  82.29 12.9 90 top
PR213  0_0402_5%  [R0402_0OHM]  83.09 12.53 90 top
PR214  0_0402_5%  [R0402_0OHM]  83.85 12.53 90 top
PR215  4.7_1206_5%  [R_1206]  84.5 32.55 0 bottom
PR216  4.7_1206_5%  [R_1206]  74.2 39.47 90 top
PR217  75_0402_5%  [R_0402]  84.61 12.53 90 top
PR218  0_0402_5%  [R0402_0OHM]  87 22.91 0 top
PR219  100K_0402_5%  [R_0402]  84.03 10.96 0 top
PR220  0_0402_5%  [R0402_0OHM]  85.75 12.53 90 top
PR221  1_0402_1%  [R_0402]  86.15 22.06 180 top
PR222  1_0402_1%  [R_0402]  87.04 21.14 180 top
PR223  0_0402_5%  [R0402_0OHM]  89.25 10.18 90 top
PR224  1M_0402_5%  [R_0402]  87.74 13.82 180 top
PR225  154K_0402_1%  [R_0402]  86.8 12.73 0 top
PR226  93.1K_0402_1%  [R_0402]  86.32 15.28 0 top
PR227  1M_0402_5%  [R_0402]  89.25 11.83 90 top
PR229  0_0201_5%  [R0201_0OHM]  85.91 18.6 0 top
PR230  1K_0402_1%  [R_0402]  218.97 69.82 0 top
PR231  499_0402_1%  [R_0402]  86.34 16.98 90 top
PR232  10K_0201_5%  [R_0201]  87.16 18.6 0 top
PR233  0_0402_5%  [R0402_0OHM]  219.88 69.06 180 top
PR234  0_0402_5%  [R0402_0OHM]  219.88 68.3 180 top
PR236  100_0402_1%  [R_0402]  86.09 19.36 0 top
PR300  0_0402_5%  [R0402_0OHM]  85.48 59.66 180 top
PR301  90.9K_0201_1%  [R_0201]  85.25 53.93 90 top
PR303  0_0603_5%  [R_0603]  83.02 54.15 0 top
PR304  26.1K_0402_1%  [R_0402]  85.48 56.11 180 top
PR306  768K_0402_1%  [R_0402]  85.16 52.2 90 top
PR307  499_0402_1%  [R_0402]  86.45 56.54 90 top
PR308  150K_0201_5%  [R_0201]  84.57 55.2 0 top
PR309  30.1K_0402_1%  [R_0402]  84.56 56.99 0 top
PR310  0_0402_5%  [R_0402]  84.57 57.86 0 top
PR311  4.7_0805_5%  [R_0805]  84.77 51.16 270 top
PR400  0_0402_5%  [R0402_0OHM]  26.21 2.64 180 top
PR401  90.9K_0201_1%  [R_0201]  22.32 3.87 90 top
PR403  0_0603_5%  [R_0603]  21.43 4.23 270 top
PR404  26.1K_0402_1%  [R_0402]  24.48 2.56 90 top
PR406  274K_0402_1%  [R_0402]  22.7 3.22 270 top
PR407  499_0402_1%  [R_0402]  23.72 2.56 90 top
PR408  150K_0201_5%  [R_0201]  22.96 4.46 270 top
PR409  13.3K_0402_1%  [R_0402]  23.64 4.29 0 top
PR410  4.7_0805_5%  [R_0805]  19.17 3.28 180 top
PR411  0_0402_5%  [R_0402]  25.31 4.37 270 top
PR412  0_0402_5%  [R0402_0OHM]  266.02 8.61 0 top
PR413  0_0201_5%  [R0201_0OHM]  270.79 8.66 270 top
PR415  0_0603_5%  [R_0603]  271.66 8.26 90 top
PR416  26.1K_0402_1%  [R_0402]  269.27 9.89 270 top
PR418  274K_0402_1%  [R_0402]  271.89 10.51 180 top
PR419  499_0402_1%  [R_0402]  270.1 9.89 270 top
PR420  150K_0201_5%  [R_0201]  271.76 2.64 180 top
PR421  13.3K_0402_1%  [R_0402]  270.08 8.22 180 top
PR422  4.7_0805_5%  [R_0805]  274.8 8.02 90 top
PR423  0_0402_5%  [R_0402]  268.25 9.99 90 top
PR501  499_0402_1%  [R_0402]  213.28 18.9 180 top
PR502  40.2K_0402_1%  [R_0402]  211.61 17.99 90 top
PR503  150K_0201_5%  [R_0201]  208.91 17.51 90 top
PR504  20K_0402_1%  [R_0402]  210.85 18.91 270 top
PR506  4.7_0805_5%  [R_0805]  208.53 24.91 0 top
PR507  0_0603_5%  [R_0603]  207.8 19.66 270 top
PR509  100K_0201_5%  [R_0201]  210.14 17.88 180 top
PR510  274K_0402_1%  [R_0402]  212.36 17.5 0 top
PR600  100K_0402_5%  [R_0402]  89.58 7.91 180 top
PR601  100K_0402_5%  [R_0402]  89.58 8.74 180 top
PR602  549K_0402_1%  [R_0402]  91.35 8.24 270 top
PR603  100K_0402_5%  [R_0402]  82.49 9.23 270 top
PR604  100K_0402_5%  [R_0402]  79.22 7.03 270 top
PR605  1M_0402_5%  [R_0402]  91.33 5.43 0 top
PR606  100K_0402_5%  [R_0402]  87.45 9.43 180 top
PR607  0_0402_5%  [R0402_0OHM]  87.45 8.66 180 top
PR608  0_0402_5%  [R0402_0OHM]  86.54 7.89 0 top
PR702  10K_0201_1%  [R_0201]  92.17 63.07 270 top
PR703  10K_0201_5%  [R_0201]  92.61 60.68 180 top
PR704  12K_0201_1%  [R_0201]  92.74 62.48 90 top
PR705  91K_0402_1%  [R_0402]  92.58 59.06 270 top
PR706  51K_0201_1%  [R_0201]  91.79 58.54 90 top
PR707  4.7_0805_5%  [R_0805]  101.19 63.35 0 top
PR708  2.2_0603_5%  [R_0603]  99.07 63 90 top
PR712  0_0402_5%  [R_0402]  91.42 62.55 90 top
PR801  0_0603_5%  [R_0603]  79.73 65.74 180 top
PR802  150K_0201_5%  [R_0201]  80.6 70.58 90 top
PR803  0_0402_5%  [R0402_0OHM]  80.86 64.49 0 top
PR804  4.7_0603_5%  [R_0603]  78.52 71.16 180 top
PR900  5.1_0402_1%  [R_0402]  139.08 14.32 0 top
PR901  150K_0201_1%  [R_0201]  141.69 6.47 90 top
PR902  2.2_0603_5%  [R_0603]  143.7 13.53 90 top
PR903  100_0201_1%  [R_0201]  155.94 15.49 180 top
PR904  2.2_0603_5%  [R_0603]  143.76 7.05 270 top
PR906  100_0201_1%  [R_0201]  155.35 16.1 0 top
PR907  0_0201_5%  [R_0201]  142.81 13.34 90 top
PR908  0_0201_5%  [R_0201]  142.23 13.35 90 top
PR910  4.7_0805_5%  [R_0805]  145.93 5.75 0 top
PR912  0_0201_5%  [R0201_0OHM]  142.29 6.46 90 top
PR915  0_0402_5%  [R0402_0OHM]  141.57 13.49 90 top
PR916  0_0402_5%  [R0402_0OHM]  140.81 13.49 90 top
PR1100  9.09K_0402_1%  [R_0402]  93.09 45.64 90 top
PR1101  49.9K_0402_1%  [R_0402]  93.05 47.65 90 top
PR1102  4.7_0402_5%  [R_0402]  93.93 48.91 0 top
PR1103  0_0201_5%  [R0201_0OHM]  93.09 43.93 90 top
PR1104  2M_0402_1%  [R_0402]  93.9 44.41 0 top
PR1106  133K_0402_1%  [R_0402]  94.82 43.52 180 top
PR1107  1.5K_0402_1%  [R_0402]  96.57 42.69 90 top
PR1108  1.5K_0402_1%  [R_0402]  95.68 42.69 90 top
PR1109  10K_0201_5%  [R_0201]  99.69 52.41 180 top
PR1110  0_0402_5%  [R0402_0OHM]  93.91 42.61 0 top
PR1111  10K_0201_5%  [R_0201]  97.79 51.21 270 top
PR1112  10K_0201_5%  [R_0201]  96.7 53.56 270 top
PR1113  10K_0201_5%  [R_0201]  99.09 53.58 270 top
PR1114  1.91K_0402_1%  [R_0402]  100.12 51.69 270 top
PR1115  0_0201_5%  [R0201_0OHM]  97.22 50.62 90 top
PR1116  0_0402_5%  [R0402_0OHM]  95.87 41.81 0 top
PR1117  806_0402_1%  [R_0402]  98.85 43.66 180 top
PR1118  0_0402_5%  [R0402_0OHM]  97.44 52.53 90 top
PR1119  100_0201_1%  [R_0201]  123.58 40.74 180 top
PR1120  4.99K_0402_1%  [R_0402]  98.85 41.76 180 top
PR1121  0_0402_5%  [R0402_0OHM]  98.33 52.53 90 top
PR1122  0_0402_5%  [R0402_0OHM]  100.76 42.9 180 top
PR1123  75_0402_5%  [R_0402]  99.22 50.78 90 top
PR1124  0_0402_5%  [R0402_0OHM]  100.76 43.66 180 top
PR1125  0_0201_5%  [R0201_0OHM]  100.89 50.77 0 top
PR1126  100_0201_1%  [R_0201]  123.58 41.38 180 top
PR1127  45.3_0402_1%  [R_0402]  104.72 48.79 180 top
PR1128  100_0402_1%  [R_0402]  104.72 49.68 180 top
PR1129  45.3_0402_1%  [R_0402]  104.72 47.91 180 top
PR1130  0_0402_5%  [R0402_0OHM]  102.03 48.79 0 top
PR1131  0_0402_5%  [R0402_0OHM]  102.03 49.68 0 top
PR1132  0_0402_5%  [R0402_0OHM]  102.03 47.91 0 top
PR1133  60.4K_0402_1%  [R_0402]  102 44.83 0 top
PR1134  61.9K_0402_1%  [R_0402]  103.83 46.43 270 top
PR1200  0_0402_5%  [R0402_0OHM]  102.55 33.37 0 top
PR1201  4.7_1206_5%  [R_1206]  108.54 41.87 180 top
PR1202  0_0402_5%  [R0402_0OHM]  102.43 24.15 0 top
PR1203  4.7_1206_5%  [R_1206]  106.33 23.35 0 top
PR1204  0_0201_5%  [R0201_0OHM]  101.15 34.39 0 top
PR1205  0_0201_5%  [R0201_0OHM]  101.7 24.45 90 top
PR1300  1K_0402_5%  [R_0402]  112.63 24.36 180 top
PR1400  0_0201_5%  [R0201_0OHM]  213.04 30.33 0 top
PR1401  2.2_0603_5%  [R_0603]  214.29 31.09 90 top
PR1403  499_0402_1%  [R_0402]  212.87 28.17 0 top
PR1406  100K_0201_5%  [R_0201]  213.81 28.87 180 top
PR1408  0_0402_5%  [R0402_0OHM]  213.79 27.41 180 top
PR1409  5.1_0402_1%  [R_0402]  212.92 29.59 0 top
PR1411  4.7_0805_5%  [R_0805]  220.4 32.7 270 top
PR1502  0_0603_5%  [R_0603]  195.11 5.71 180 top
PR1503  499_0402_1%  [R_0402]  195.96 5.33 0 top
PR1507  150K_0201_5%  [R_0201]  196.15 10.82 180 top
PR1509  4.7_0805_5%  [R_0805]  192.7 11.54 0 top
PT200  PAD~D  [TPC12]  75.88 21.53 0 top
PU200  ISL9538BHRTZ-T_TQFN32_4X4  [ISL88738HRTZ-T_TQFN32_4X4]  83.76 19.32 270 top
PU300  -  [NB502GQ-Z_QFN16_3X3]  82.07 58.03 270 top
PU400  -  [NB502GQ-Z_QFN16_3X3]  24.19 6.71 180 top
PU401  -  [NB502GQ-Z_QFN16_3X3]  269 5.86 0 top
PU500  -  [NB691GG-Z_QFN11_2X2]  211.03 21.04 180 top
PU600  -  [SN74LVC1G123DCUR_VSSOP8]  87.09 6.96 270 top
PU700  -  [RT6243BGQVF_VQFN18_3P5X3P5]  94.92 59.08 90 top
PU800  -  [NB691GG-Z_QFN11_2X2]  82.15 68.13 180 top
PU900  -  [MP2941GL-Z_QFN19_3X4]  140.91 11.28 0 top
PU1100  -  [MP2940AGRT-0010-Z_TQFN28_4X4]  97.21 45.31 90 top
PU1200  -  [MP86902-BGLT-Z_TQFN21-15_3X4]  103.36 36.38 180 top
PU1201  -  [MP86902-BGLT-Z_TQFN21-15_3X4]  103.34 27.21 180 top
PU1400  -  [NB693GQ-Z_QFN16_3X3]  216.1 27.32 90 top
PU1500  -  [NB691GG-Z_QFN11_2X2]  197.56 8.27 180 top
Q3  -  [L2N7002WT1G_SC-70-3]  184.18 19.53 270 top
Q15  S TR AO6405 1P TSOP6  [SI3457BDV-T1-E3_TSOP6]  102.43 69.29 180 top
Q16  -  [L2N7002DW1T1G_SC88-6]  87.32 65.42 270 top
Q30  -  [PMDXB600UNE_DFN1010B-6]  210.69 70.29 0 top
Q124  PJQ1900_DFN3L  [PMBT3904MB_SOT883B]  176.72 63.47 270 top
Q348  -  [L2N7002WT1G_SC-70-3]  184.31 16.99 270 top
Q349  PJ2301_SOT23-3  [LP2301ALT1G_SOT23-3]  179.32 13.69 90 top
Q350  PJQ1900_DFN3L  [PMBT3904MB_SOT883B]  176.88 64.08 180 bottom
QC1  PJQ1900_DFN3L  [PMBT3904MB_SOT883B]  159.18 78.09 90 bottom
QC2  -  [PMDXB600UNE_DFN1010B-6]  220.92 46.87 180 top
QE3  -  [PMBT3904MB_SOT883B]  245.67 14.26 270 top
QE4  -  [PMBT3904MB_SOT883B]  145.3 26.52 90 bottom
QE8  -  [PMBT3904MB_SOT883B]  191.34 55.22 270 bottom
QE10  -  [PMBT3904MB_SOT883B]  84.15 23.98 90 top
QE14  -  [PMBT3904MB_SOT883B]  137.64 67.89 180 bottom
QE15  -  [L2N7002WT1G_SC-70-3]  200.69 56.62 270 top
QE16  -  [LMBT3904WT1G_SC70-3]  200.69 59.08 90 top
QE17  -  [PMBT3904MB_SOT883B]  211.81 39.22 270 top
QE18  -  [2N7002KDW_SOT363-6]  199.3 54.34 270 top
QE19  -  [L2N7002WT1G_SC-70-3]  216.89 52.1 0 top
QE22  -  [PMBT3904MB_SOT883B]  217.84 71.57 0 top
QE23  -  [L2N7002WT1G_SC-70-3]  215.87 71.34 0 top
QE25  -  [LMBT3904WT1G_SC70-3]  198.78 17.82 90 top
QF1  PJQ1900_DFN3L  [PMBT3904MB_SOT883B]  56.69 17.32 270 bottom
QF2  PJQ1900_DFN3L  [PMBT3904MB_SOT883B]  59.82 13.37 0 top
QM1  -  [2N7002KDW_SOT363-6]  188.5 26.88 90 top
QR1  PJQ1900_DFN3L  [PMBT3904MB_SOT883B]  279.5 30.36 180 top
QRTC1  -  [L2N7002WT1G_SC-70-3]  38.45 11.59 270 top
QT1  PJQ1900_DFN3L  [PMBT3904MB_SOT883B]  9.18 36.3 90 top
QT2  PJQ1900_DFN3L  [PMBT3904MB_SOT883B]  286.28 23.75 90 top
QV18  LMBT3906N3T5G_SOT883-3  [MMBT3906LP-7B_X1-DFN1006-3]  122.8 78.92 0 bottom
QV19  LMBT3904N3T5G_SOT883-3  [MMBT3904LP-7B_X1-DFN1006-3]  124.74 78.92 0 bottom
QV20  LMBT3906N3T5G_SOT883-3  [MMBT3906LP-7B_X1-DFN1006-3]  126.68 78.92 0 bottom
QV21  LMBT3904N3T5G_SOT883-3  [MMBT3904LP-7B_X1-DFN1006-3]  128.65 78.92 0 bottom
QW1  PJQ1900_DFN3L  [PMBT3904MB_SOT883B]  195.94 58.19 270 top
QW2  -  [PMDXB600UNE_DFN1010B-6]  195.96 58.54 180 bottom
QZ20  -  [LMUN5111T1G_SC70-3]  197.84 13.82 180 top
R24  0_0603_5%  [R0603_0OHM]  104.3 70.97 0 top
R25  90.9K_0201_1%  [R_0201]  107.25 68.17 0 top
R29  100K_0201_5%  [R_0201]  87.75 66.39 180 top
R30  100K_0402_5%  [R_0402]  96.29 69.23 270 top
R31  100K_0201_5%  [R_0201]  188.09 42.07 180 top
R32  10K_0201_5%  [R_0201]  187.51 43.79 0 top
R36  10K_0201_1%  [R_0201]  65.67 13.63 180 top
R37  10K_0201_1%  [R_0201]  65.67 14.2 180 top
R38  10K_0201_1%  [R_0201]  66.99 9.75 0 top
R39  10K_0201_1%  [R_0201]  236.48 2.01 180 top
R40  10K_0201_1%  [R_0201]  234.69 2.01 0 top
R41  10K_0201_1%  [R_0201]  232.66 9.56 0 top
R54  0_0201_5%  [R_0201]  210.6 12.09 0 top
R87  0.01_0603_1%  [R_0603]  99.03 68.35 90 top
R111  0_0201_5%  [R_0201]  105.95 14.54 90 bottom
R112  51_0201_5%  [R_0201]  112.68 3.11 90 bottom
R113  0_0201_5%  [R_0201]  113.95 3.11 90 bottom
R114  0_0201_5%  [R_0201]  114.59 3.11 90 bottom
R123  0.01_0402_1%  [R_0402]  109.14 21.25 180 bottom
R137  10K_0201_5%  [R_0201]  112.05 3.11 90 bottom
R138  0_0402_5%  [R_0402]  122.97 2.75 90 bottom
R140  1K_0201_5%  [R_0201]  113.06 14.54 90 bottom
R141  1K_0201_5%  [R_0201]  113.82 14.54 90 bottom
R142  1K_0201_5%  [R_0201]  114.59 14.54 90 bottom
R143  1K_0201_5%  [R_0201]  115.35 14.54 90 bottom
R144  1K_0201_5%  [R_0201]  116.11 14.54 90 bottom
R145  1K_0201_5%  [R_0201]  116.87 14.54 90 bottom
R146  1K_0201_5%  [R_0201]  117.63 14.54 90 bottom
R147  1K_0201_5%  [R_0201]  118.4 14.54 90 bottom
R148  1K_0201_5%  [R_0201]  119.16 14.54 90 bottom
R149  1K_0201_5%  [R_0201]  119.92 14.54 90 bottom
R150  1K_0201_5%  [R_0201]  120.81 14.54 90 bottom
R151  1K_0201_5%  [R_0201]  121.51 14.54 90 bottom
R152  1K_0201_5%  [R_0201]  122.21 14.54 90 bottom
R153  1K_0201_5%  [R_0201]  122.97 14.54 90 bottom
R154  1K_0201_5%  [R_0201]  123.73 14.54 90 bottom
R155  1K_0201_5%  [R_0201]  124.49 14.54 90 bottom
R156  0_0201_5%  [R0201_0OHM]  109.51 3.69 270 bottom
R157  0_0201_5%  [R_0201]  125.06 3.69 270 bottom
R160  10K_0201_5%  [R_0201]  113.06 15.81 90 bottom
R161  10K_0201_5%  [R_0201]  113.82 15.81 90 bottom
R162  10K_0201_5%  [R_0201]  114.59 15.81 90 bottom
R163  10K_0201_5%  [R_0201]  115.35 15.81 90 bottom
R164  10K_0201_5%  [R_0201]  116.11 15.81 90 bottom
R165  10K_0201_5%  [R_0201]  116.87 15.81 90 bottom
R166  10K_0201_5%  [R_0201]  117.63 15.81 90 bottom
R167  10K_0201_5%  [R_0201]  118.4 15.81 90 bottom
R168  10K_0201_5%  [R_0201]  119.16 15.81 90 bottom
R169  10K_0201_5%  [R_0201]  119.92 15.81 90 bottom
R170  10K_0201_5%  [R_0201]  120.81 15.81 90 bottom
R171  10K_0201_5%  [R_0201]  121.51 15.81 90 bottom
R172  10K_0201_5%  [R_0201]  122.21 15.81 90 bottom
R173  10K_0201_5%  [R_0201]  122.97 15.81 90 bottom
R174  10K_0201_5%  [R_0201]  123.73 15.81 90 bottom
